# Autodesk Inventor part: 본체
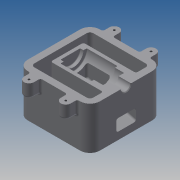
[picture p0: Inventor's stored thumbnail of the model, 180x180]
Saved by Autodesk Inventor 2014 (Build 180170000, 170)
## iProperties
Created: 2018-01
Part Number: 본체
Material: Generic
Document SubType Name: Modeling
Designer: kb542
Density: 1 g/cm^3
Appearance: Default
Author: kb542
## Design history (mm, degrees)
sketch "스케치1"
  geometry: L1 (-55, -55)-(55, -55); L2 (55, -55)-(55, 55); L3 (55, 55)-(-55, 55); L4 (-55, 55)-(-55, -55); L5 (-55, -55)-(55, 55); L6 (55, -55)-(-55, 55); 1 further point
  constraints: 12 end point, 2 midpoint, 2 parallel, 1 horizontal, 1 perpendicular
  dimensions: "d0" = 110 distance of L2.end L3.end; "d1" = 110 distance of L1.end L2.end
extrude "돌출1" new body sketch "스케치1" stored distance "d2" = 65; taper "d3" = 0 deg
sketch "스케치2"
  geometry: L1 (55, -55)-(55, 55) reference; L2 (55, 55)-(-55, 55) reference; L3 (-45, -45)-(45, -45); L4 (45, -45)-(45, 45); L5 (45, 45)-(-45, 45); L6 (-45, 45)-(-45, -45); L7 (-45, -45)-(45, 45); L8 (45, -45)-(-45, 45); 1 further point
  constraints: 12 end point, 2 midpoint, 2 parallel, 1 horizontal, 1 perpendicular
  dimensions: "d4" = 10 distance between parallel lines of L5 L2; "d5" = 10 distance between parallel lines of L1 L4
extrude "돌출2" cut sketch "스케치2" stored distance "d6" = 65; taper "d7" = 0 deg
sketch "스케치4"
  geometry: L1 (-45, 32.5)-(-45, -32.5) reference; L2 (-45, 32.5)-(45, 32.5) reference; L3 (55, 32.5)-(55, -32.5) reference; L4 (35, 32.5)-(35, -2.5); L5 (35, -2.5)-(-45, -23.936); L6 (35, 32.5)-(-45, 32.5); L7 (-45, -23.936)-(-45, 32.5); 1 further point
  constraints: 8 end point, 2 point on line, 1 collinear, 1 parallel, 1 perpendicular
  dimensions: "d11" = 20 distance between parallel lines of L3 L4; "d12" = 30 vertical distance of L3.end L4.end; "d13" = 105 deg angle of L1 L5
extrude "돌출3" join sketch "스케치4" stored distance "d14" = 50; taper "d15" = 0 deg
sketch "스케치5"
  geometry: L1 (-55, -32.5)-(-55, 32.5) reference; L2 (55, 32.5)-(-55, 32.5) reference; L3 (-55, 25)-(-36, 25); L4 (-36, 25)-(-36, 16.5); L5 (-36, 16.5)-(-22, 16.5); L6 (-22, 16.5)-(-22, 12.5); L7 (-22, 12.5)-(25, 12.5); L8 (25, 12.5)-(25, 17.5); L9 (30, 32.5)-(-55, 32.5); L10 (-55, 32.5)-(-55, 25); L11 (25, 17.5)-(30, 17.5); L12 (30, 17.5)-(30, 32.5); 1 further point
  constraints: 20 end point, 5 perpendicular, 3 parallel, 2 collinear, 1 point on line
  dimensions: "d16" = 20 distance between parallel lines of L7 L2; "d17" = 16 distance between parallel lines of L5 L2; "d18" = 7.5 distance between parallel lines of L2 L3; "d20" = 19 distance of L3.start L3.end; "d21" = 14 distance of L4.end L5.end; "d22" = 47 distance of L6.end L7.end; "d23" = 5 distance of L8.end L11.end; "d24" = 15 distance between parallel lines of L2 L11
revolve "회전1" sketch "스케치5" stored, may be unused: angle "d25" = 90 deg
sketch "스케치8"
  geometry: L1 (-55, -3.439)-(-55, -21.439); L2 (-55, -3.439)-(-17, 6.743); L3 (35, -2.5)-(-45, -23.936) reference; L4 (20, -1.343)-(-55, -21.439); L5 (-55, -32.5)-(-55, 32.5) reference; L6 (20, -1.343)-(20, 32.5); L7 (-17, 6.743)-(-17, 32.5); L8 (-22, 12.5)-(25, 12.5) reference; L9 (-17, 32.5)-(20, 32.5); L10 (-36, 32.5)-(-22, 32.5) reference; 3 further points
  constraints: 12 end point, 3 parallel, 2 midpoint, 1 collinear, 1 point on line, 1 vertical, 1 vertical alignment
  dimensions: "d34" = 75 deg angle of L2 L1; "d35" = 18 distance of L1.start L1.end; "d36" = 5 distance between parallel lines of L3 L4; "d38" = 37 distance between parallel lines of L6 L7
extrude "돌출4" cut sketch "스케치8" stored distance "d39" = 30; taper "d40" = 0 deg
fillet "모깎기1" dims "d41" = 15, "d42" = 5
sketch "스케치9"
  geometry: L1 (40, 55)-(-40, 55) reference; L2 (-55, 40)-(-55, -40) reference; L3 (-28, 45)-(-28, 65); L4 (-35.5, 55)-(-35.5, 65); L5 (-20.5, 65)-(-20.5, 55); L6 (-35.5, 55)-(-20.5, 55); A1 r 7.5 centre (-28, 65) between (-20.5, 65) and (-35.5, 65); 3 further points
  constraints: 10 end point, 2 midpoint, 2 point on circle, 2 tangent, 1 centre point, 1 coincident, 1 collinear, 1 parallel, 1 perpendicular, 1 vertical alignment
  dimensions: "d43" = 27 distance from line of L3.end L2; "d44" = 10 distance from line of L3.end L1; "d45" = 7.5 radius of A1
extrude "돌출5" join sketch "스케치9" distance "d46" = 20; taper "d47" = 0 deg
sketch "스케치10"
  geometry: A1 r 7.5 centre (-28, 65) between (-20.5, 65) and (-35.5, 65) reference; 2 further points
  constraints: 1 coincident
hole "구멍1" sketch "스케치10" at (-28, 65) diameter "d48" = 3.242; stored, may be unused: countersink angle "d52" = 90 deg, drill point angle "d54" = 118 deg; dims "d49" = 9, "d50" = 4, "d51" = 2, "d53" = 11
fillet "모깎기2" dims "d55" = 3
fillet "모깎기3" dims "d56" = 3
sketch "스케치11"
  geometry: L1 (55, -40)-(55, -7.5) reference; L2 (-55, 40)-(-55, -40) reference; L3 (-40, -55)-(40, -55) reference; L4 (-28, -65)-(-28, -45); L5 (-35.5, -65)-(-35.5, -55); L6 (-20.5, -55)-(-20.5, -65); L7 (-35.5, -55)-(-20.5, -55); A1 r 7.5 centre (-28, 65) between (-20.5, 65) and (-35.5, 65) reference; A2 r 7.5 centre (-28, -65) between (-35.5, -65) and (-20.5, -65); 3 further points
  constraints: 10 end point, 2 midpoint, 2 parallel, 2 point on circle, 2 point on line, 2 tangent, 1 centre point, 1 coincident, 1 equal radius, 1 vertical alignment
  dimensions: "d60" = 10 distance from line of L3 L4.start; "d61" = 27 distance from line of L2 L4.start
extrude "돌출6" join sketch "스케치11" distance "d62" = 20; taper "d63" = 0 deg
sketch "스케치12"
  geometry: A1 r 7.5 centre (-28, -65) between (-35.5, -65) and (-20.5, -65) reference; 2 further points
  constraints: 1 coincident
hole "구멍2" sketch "스케치12" at (-28, -65) diameter "d64" = 3.242; stored, may be unused: countersink angle "d68" = 90 deg, drill point angle "d70" = 118 deg; dims "d65" = 9, "d66" = 4, "d67" = 2, "d69" = 11
fillet "모깎기4" dims "d71" = 3
fillet "모깎기5" dims "d72" = 3
fillet "모깎기6" dims "d76" = 3
fillet "모깎기7" dims "d77" = 1, "d78" = 3
fillet "모깎기8" dims "d79" = 3
fillet "모깎기9" dims "d80" = 3
sketch "스케치13"
  geometry: L1 (0, 0)-(80, 0) reference; 2 further points
  constraints: 1 vertical alignment, 1 other
  dimensions: "d81" = 20 distance from line of point (40, -20) L1
feature "엠보싱1" sketch "스케치13" dims "d0" = 110, "d1" = 110, "d82" = 0.5, "d83" = 0
chamfer "모따기1" distance "d84" = 1; stored, may be unused: second distance "d85" = 2, angle "d86" = 45 deg
node "솔리드1"
pattern_linear "직사각형 패턴1" dims "d59" = 56
pattern_linear "직사각형 패턴2" dims "d75" = 56
